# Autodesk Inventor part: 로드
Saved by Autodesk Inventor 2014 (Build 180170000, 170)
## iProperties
Created: 2026-03
Part Number: 로드
Material: 일반
Document SubType Name: Modeling
Designer: dg
Density: 1 g/cm^3
Appearance: 기본값
Author: dg
Author: jhkim
Creation Date: 2025-06-27
Sending System: Autodesk Inventor 2026
Preprocessor: ST-DEVELOPER v20.1
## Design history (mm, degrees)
node "로드1"
node "솔리드1"
node "기준1"
